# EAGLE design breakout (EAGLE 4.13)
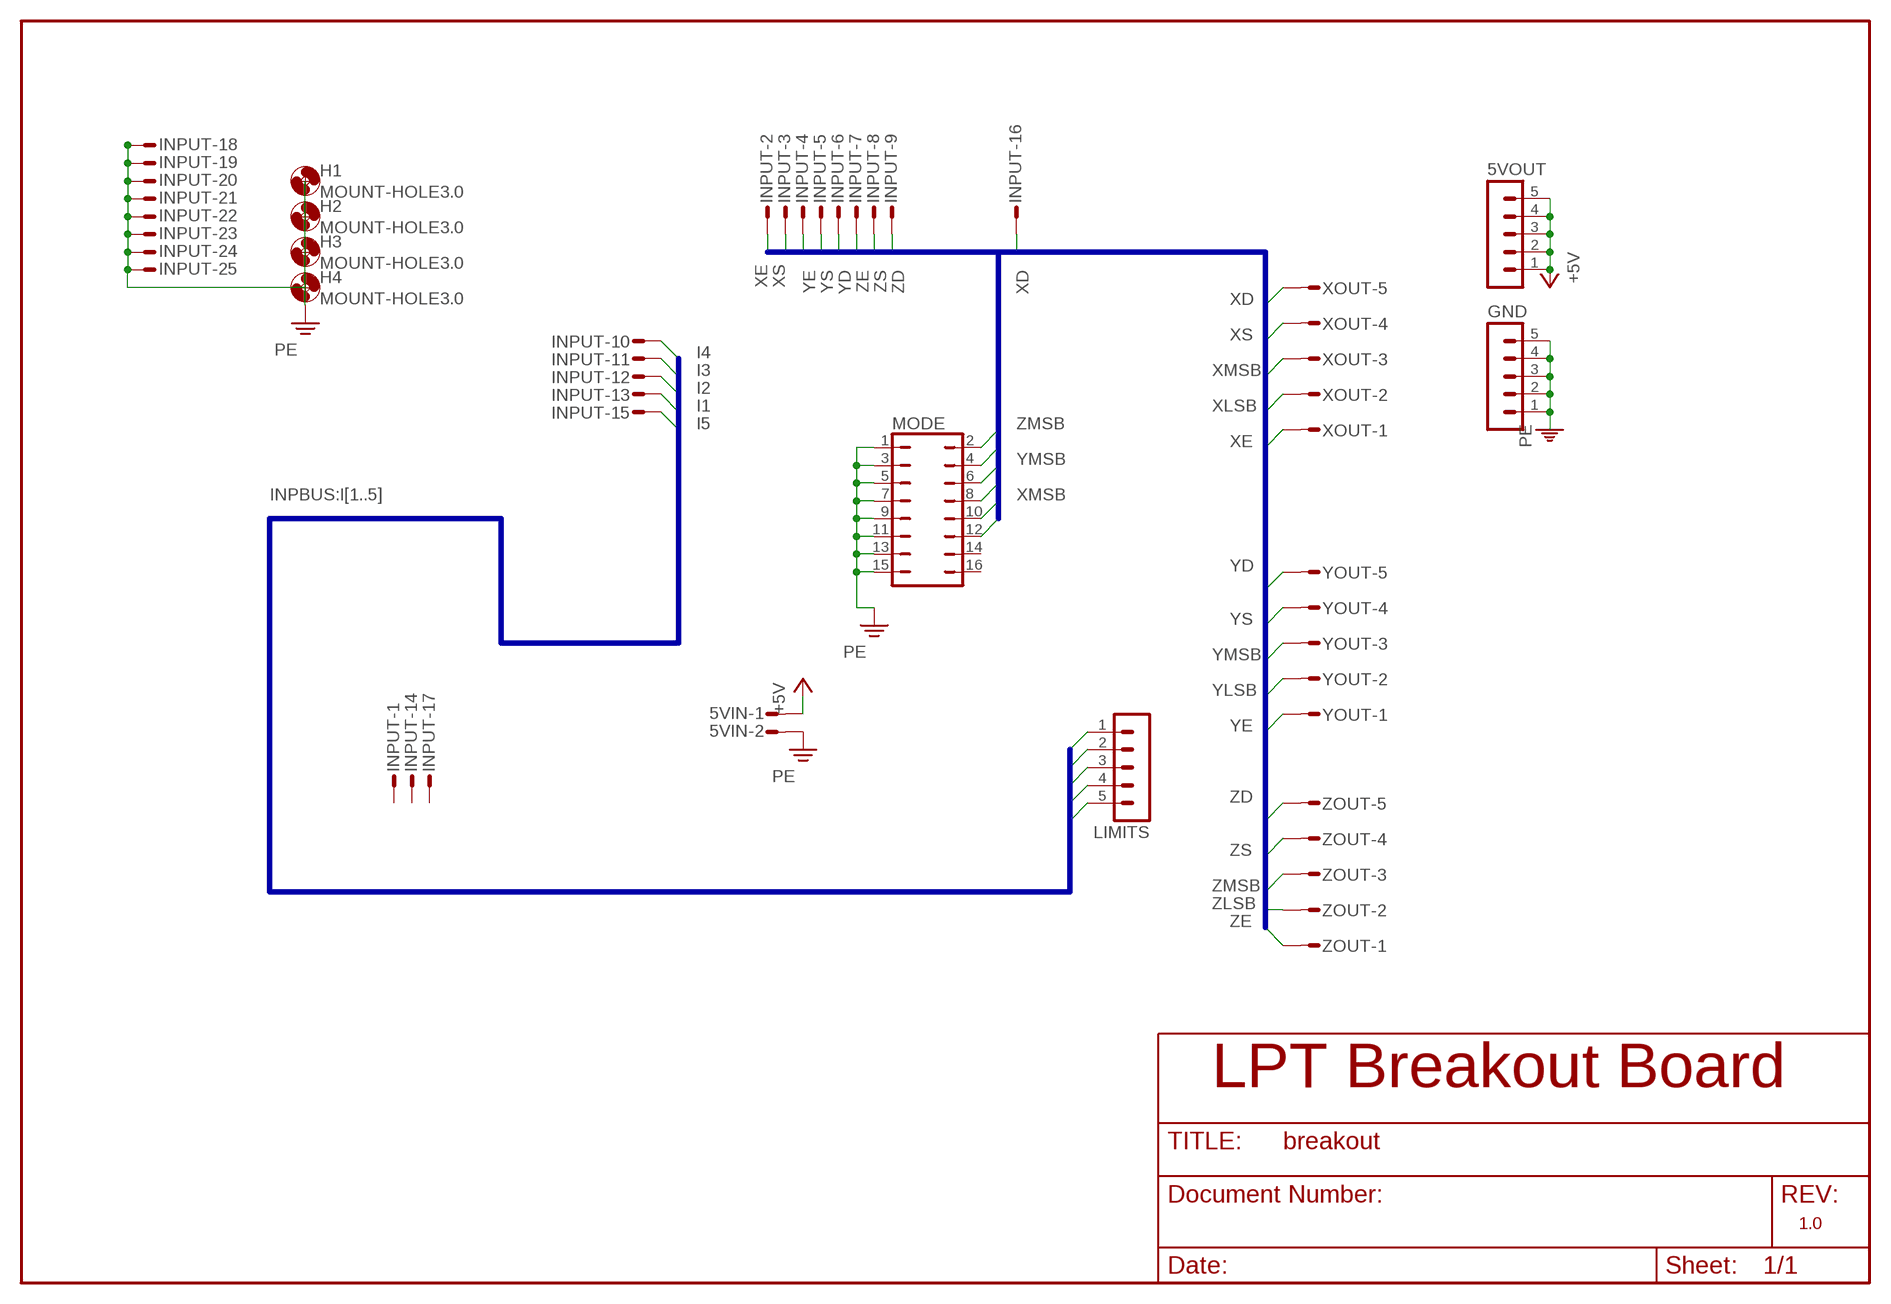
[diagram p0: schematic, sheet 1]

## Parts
5VIN  L02P  [L02P]
5VOUT  MA05-1  [MA05-1]
GND  MA05-1  [MA05-1]
H1  MOUNT-HOLE3.0  [3,0]
H2  MOUNT-HOLE3.0  [3,0]
H3  MOUNT-HOLE3.0  [3,0]
H4  MOUNT-HOLE3.0  [3,0]
INPUT  M25HS  [M25H]
LIMITS  MA05-1  [MA05-1]
MODE  JP8Q  [JP8Q]
XOUT  S05P  [S05P]
YOUT  S05P  [S05P]
ZOUT  S05P  [S05P]

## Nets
+5V: 5VIN.1 5VOUT.1 5VOUT.2 5VOUT.3 5VOUT.4 5VOUT.5
I1: INPUT.13 LIMITS.1
I2: INPUT.12 LIMITS.2
I3: INPUT.11 LIMITS.3
I4: INPUT.10 LIMITS.4
I5: INPUT.15 LIMITS.5
PE: 5VIN.2 GND.1 GND.2 GND.3 GND.4 GND.5 INPUT.18 INPUT.19 INPUT.20 INPUT.21 INPUT.22 INPUT.23 INPUT.24 INPUT.25 MODE.1 MODE.3 MODE.5 MODE.7 MODE.9 MODE.11 MODE.13 MODE.15
XD: INPUT.16 XOUT.5
XE: INPUT.2 XOUT.1
XLSB: MODE.12 XOUT.2
XMSB: MODE.10 XOUT.3
XS: INPUT.3 XOUT.4
YD: INPUT.6 YOUT.5
YE: INPUT.4 YOUT.1
YLSB: MODE.8 YOUT.2
YMSB: MODE.6 YOUT.3
YS: INPUT.5 YOUT.4
ZD: INPUT.9 ZOUT.5
ZE: INPUT.7 ZOUT.1
ZLSB: MODE.4 ZOUT.2
ZMSB: MODE.2 ZOUT.3
ZS: INPUT.8 ZOUT.4
Unconnected: INPUT.1 INPUT.14 INPUT.17 MODE.14 MODE.16

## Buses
OUTBUS:XE,XD,XS,YE,YD,YS,ZE,ZD,ZS,YMSB,YLSB,XMSB,XLSB,ZMSB,ZLSB
INPBUS:I[1..5]

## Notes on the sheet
- LPT Breakout Board
- 1.0

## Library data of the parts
5VIN = con-amp-mt:L02P: AMP MT CONNECTOR
5VOUT GND LIMITS = con-lstb:MA05-1: PIN HEADER
H1-H4 = holes:MOUNT-HOLE: MOUNTING HOLE with drill center marker
INPUT = con-subd:M25?S: SUB-D
MODE = jumper:JP8Q: JUMPER
XOUT YOUT ZOUT = con-amp-mt:S05P: AMP MT CONNECTOR

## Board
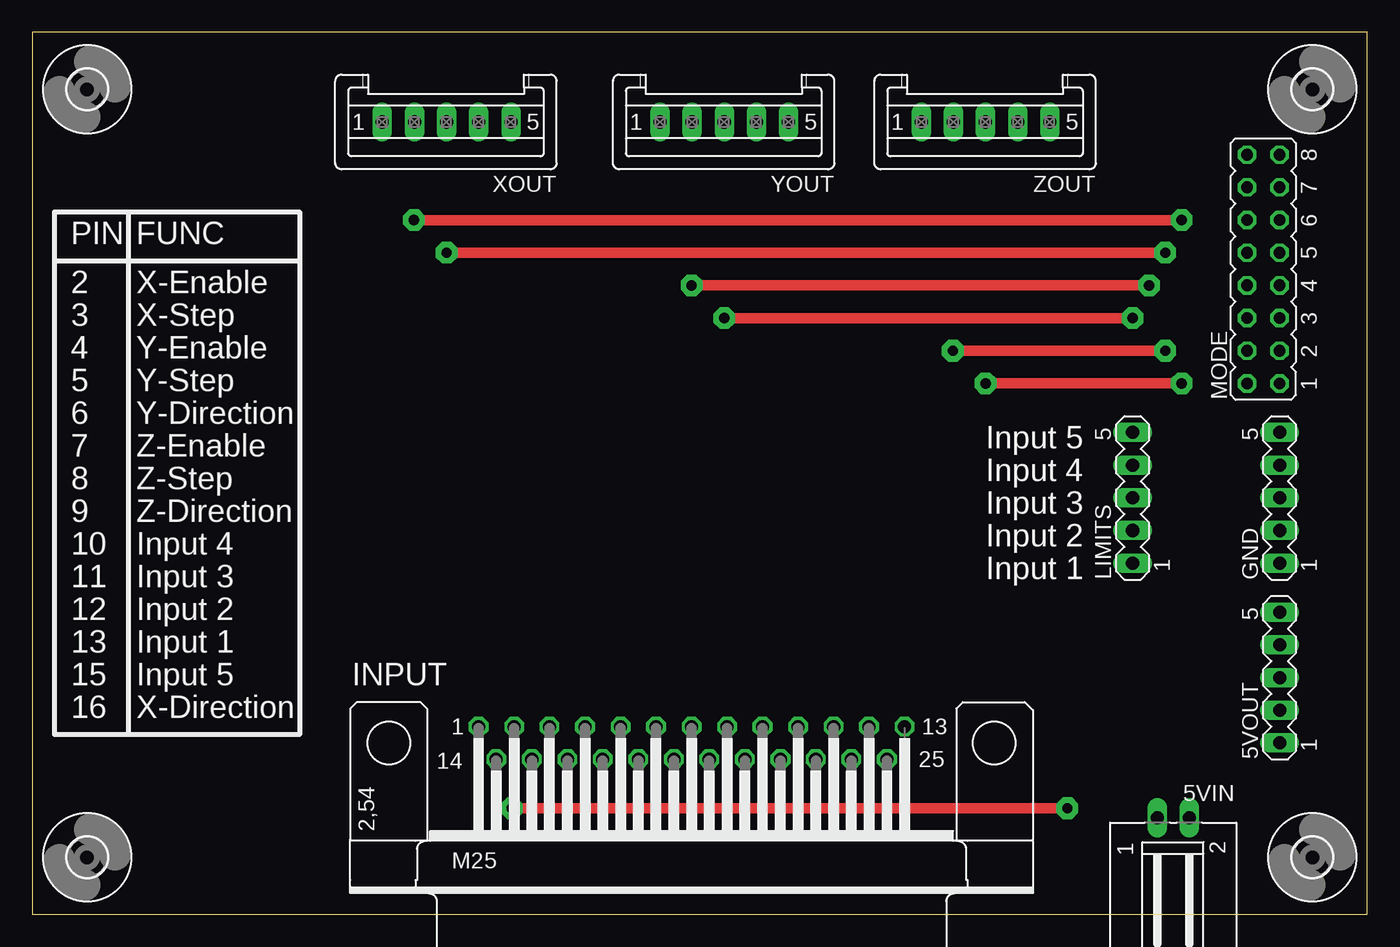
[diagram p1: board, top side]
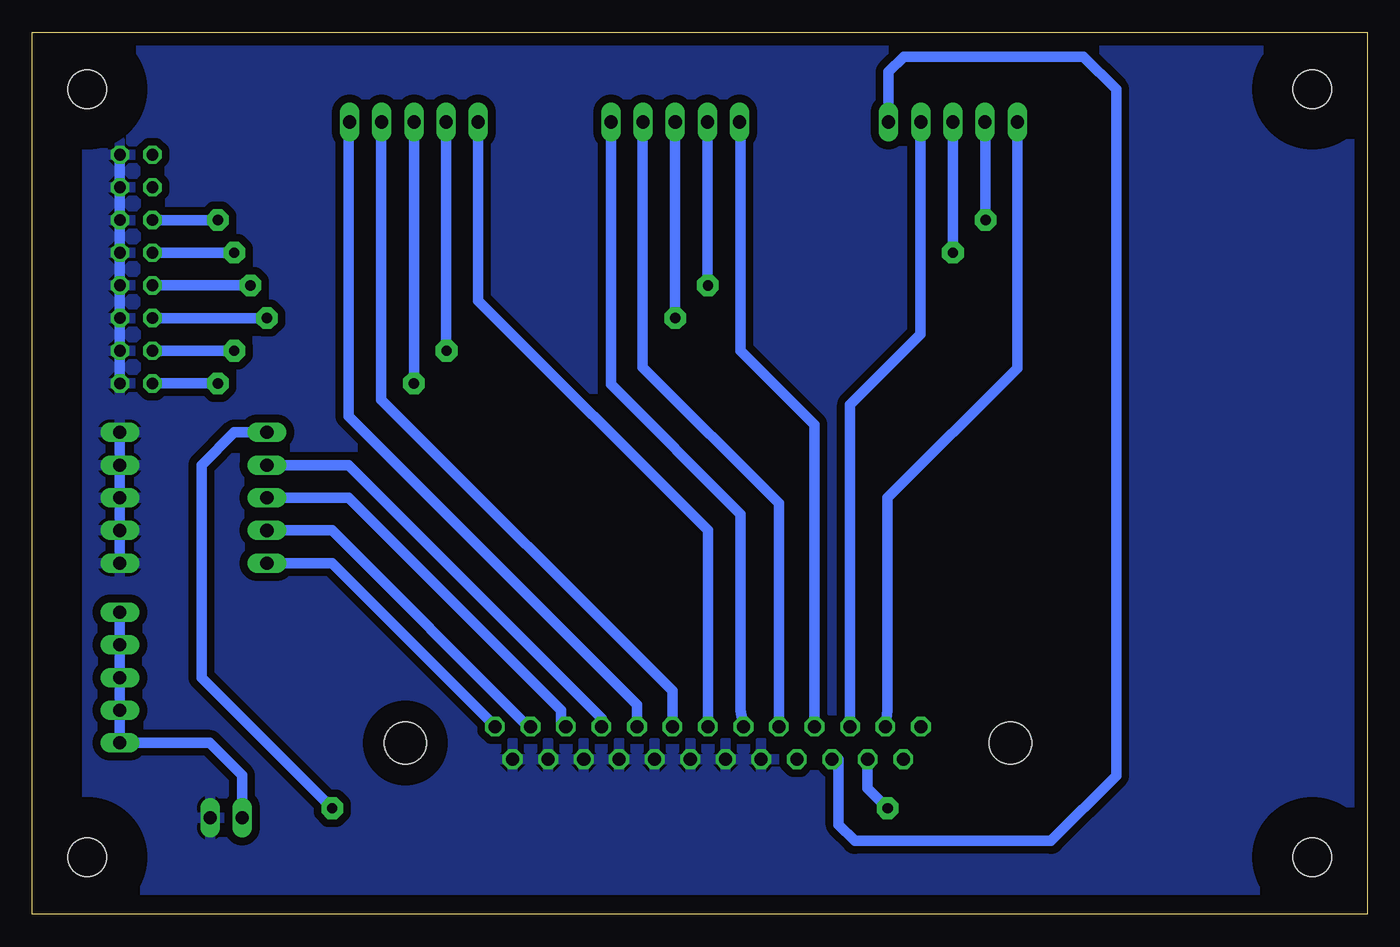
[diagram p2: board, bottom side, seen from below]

Size 103.81 x 68.57 mm. Coordinates in mm from the lower left corner, seen from the top.
Outline: 0,0 103.81,0 103.81,68.57 0,68.57 0,0
Copper layers (1*16): Top 0.035mm / dielectric 1.5mm / Bottom 0.035mm
Design rules "default": minimum track width 32mil, minimum drill 0.8mm, track to track 24mil, track to pad 24mil, pad to pad 8mil, via to via 8mil, smd to smd 8mil, copper to edge 40mil, drill to drill 8mil, minimum pad ring 10mil, minimum via ring 8mil, stop-mask expansion 4mil, vias tented up to drill 0mil, thermal gap 10mil

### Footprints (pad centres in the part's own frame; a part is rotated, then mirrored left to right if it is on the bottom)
L02P = drill 1.016 long: 1 1.25,-6.25; 2 -1.25,-6.25
MA05-1 = drill 1.016 long: 1 -5.08,0; 2 -2.54,0; 3 0,0; 4 2.54,0; 5 5.08,0
3,0 = hole 3: 0,0
M25H = drill 1.016 octagon: 1 -16.561,1.27; 2 -13.792,1.27; 3 -11.049,1.27; 4 -8.28,1.27; 5 -5.512,1.27; 6 -2.769,1.27; 7 0,1.27; 8 2.769,1.27; 9 5.512,1.27; 10 8.28,1.27; 11 11.049,1.27; 12 13.792,1.27; 13 16.561,1.27; 14 -15.189,-1.27; 15 -12.421,-1.27; 16 -9.652,-1.27; 17 -6.909,-1.27; 18 -4.14,-1.27; 19 -1.372,-1.27; 20 1.372,-1.27; 21 4.14,-1.27; 22 6.909,-1.27; 23 9.652,-1.27; 24 12.421,-1.27; 25 15.189,-1.27 | hole 3.302: 23.52,0; -23.52,0
JP8Q = drill 0.914 octagon: 1 -8.89,-1.27; 2 -8.89,1.27; 3 -6.35,-1.27; 4 -6.35,1.27; 5 -3.81,-1.27; 6 -3.81,1.27; 7 -1.27,-1.27; 8 -1.27,1.27; 9 1.27,-1.27; 10 1.27,1.27; 11 3.81,-1.27; 12 3.81,1.27; 13 6.35,-1.27; 14 6.35,1.27; 15 8.89,-1.27; 16 8.89,1.27
S05P = drill 1.016 long: 1 5,0; 2 2.5,0; 3 0,0; 4 -2.5,0; 5 -5,0

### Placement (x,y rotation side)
5VIN  88.73,1.27 180 top
5VOUT  96.99,18.41 90 top
GND  96.99,32.38 90 top
H1  99.53,4.44 0 top
H2  99.53,64.13 0 top
H3  4.28,4.44 0 top
H4  4.28,64.13 0 top
INPUT  51.27,13.33 0 top
LIMITS  85.56,32.38 90 top
MODE  95.72,50.16 90 top
XOUT  32.22,61.59 180 top
YOUT  53.81,61.59 180 top
ZOUT  74.13,61.59 180 top

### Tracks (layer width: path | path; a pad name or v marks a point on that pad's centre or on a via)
+5V
  Bottom 0.813: 5VOUT.5 5VOUT.4 5VOUT.3 5VOUT.2 5VOUT.1 90,13.33 87.48,10.81 5VIN.1
I1
  Bottom 0.813: INPUT.13 67.78,14.6 80.48,27.3 LIMITS.1
I2
  Bottom 0.813: INPUT.12 65.24,14.6 80.48,29.84 LIMITS.2
I3
  Bottom 0.813: LIMITS.3 79.21,32.38 62.7,15.87 62.7,14.6 INPUT.11
I4
  Bottom 0.813: INPUT.10 59.55,15.26 79.21,34.92 LIMITS.4
I5  (via drill 0.8 pad 1.68)
  Top 0.813: v37.3,8.25 v80.48,8.25
  Bottom 0.813: INPUT.15 38.85,9.8 v37.3,8.25 | v80.48,8.25 90.64,18.41 90.64,34.92 88.1,37.46 LIMITS.5
PE
  Bottom 0.813: MODE.15 MODE.13 MODE.11 MODE.9 MODE.7 MODE.5 MODE.3 MODE.1 | GND.1 GND.2 GND.3 GND.4 GND.5
  pour Bottom (isolate 0.61): 0.47,67.94 0.47,1.9 99.53,1.9 99.53,67.94
XD
  Bottom 0.813: XOUT.5 37.22,65.48 36.03,66.67 22.06,66.67 19.52,64.13 19.52,10.79 24.6,5.71 39.84,5.71 41.11,6.98 41.11,12.06 INPUT.16
XE
  Bottom 0.813: XOUT.1 27.22,42.46 37.3,32.38 37.3,15.87 INPUT.2
XLSB  (via drill 0.8 pad 1.68)
  Top 0.813: v29.68,53.97 v89.37,53.97
  Bottom 0.813: XOUT.2 29.68,61.59 v29.68,53.97 | v89.37,53.97 MODE.12
XMSB  (via drill 0.8 pad 1.68)
  Top 0.813: v32.22,51.43 v88.1,51.43
  Bottom 0.813: v32.22,51.43 XOUT.3 | v88.1,51.43 MODE.10
XS
  Bottom 0.813: INPUT.3 40.22,39.62 34.76,45.08 34.76,61.59 XOUT.4
YD
  Bottom 0.813: YOUT.5 58.81,41.19 48.73,31.11 48.73,15.87 INPUT.6
YE
  Bottom 0.813: INPUT.4 42.99,38.07 48.73,43.81 48.73,61.59 YOUT.1
YLSB  (via drill 0.8 pad 1.68)
  Top 0.813: v51.27,48.89 v86.83,48.89
  Bottom 0.813: YOUT.2 51.31,48.93 v51.27,48.89 | v86.83,48.89 MODE.8
YMSB  (via drill 0.8 pad 1.68)
  Top 0.813: v53.81,46.35 v85.56,46.35
  Bottom 0.813: v53.81,46.35 YOUT.3 | v85.56,46.35 MODE.6
YS
  Bottom 0.813: INPUT.5 45.76,31.95 56.35,42.54 56.35,61.59 YOUT.4
ZD
  Bottom 0.813: INPUT.9 56.78,16.3 79.21,38.73 79.21,61.59 ZOUT.5
ZE
  Bottom 0.813: ZOUT.1 69.13,47.7 51.27,29.84 INPUT.7
ZLSB  (via drill 0.8 pad 1.68)
  Top 0.813: v71.59,43.81 v88.1,43.81
  Bottom 0.813: ZOUT.2 71.63,43.85 v71.59,43.81 | v88.1,43.81 MODE.4
ZMSB  (via drill 0.8 pad 1.68)
  Top 0.813: v74.13,41.27 v89.37,41.27
  Bottom 0.813: v74.13,41.27 ZOUT.3 | v89.37,41.27 MODE.2
ZS
  Bottom 0.813: INPUT.8 54.04,17.37 76.67,40 76.67,61.59 ZOUT.4

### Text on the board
tPlace: PIN | FUNC | 2 | X-Enable | 3 | X-Step | 4 | Y-Enable | 5 | Y-Step | 6 | Y-Direction | Input 5 | 7 | Z-Enable | 8 | Z-Step | Input 4 | Input 3 | 9 | Z-Direction | Input 2 | 10 | Input 4 | Input 1 | 11 | Input 3 | 12 | Input 2 | 13 | Input 1 | 15 | Input 5 | 16 | X-Direction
